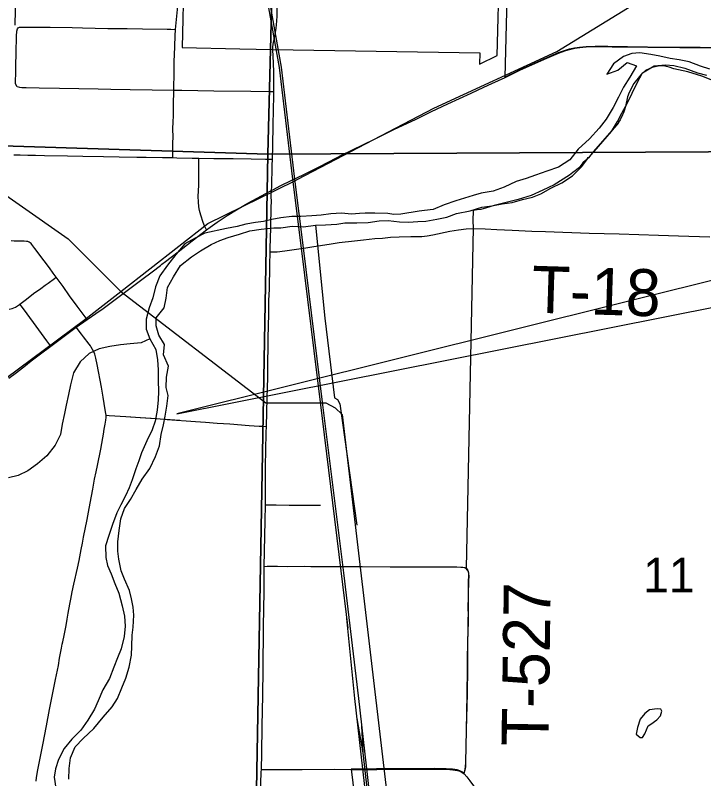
# Model space of a CAD drawing. Extents: x 0 to 34, y 0 to 22.
# Drawn here: x 4.781 to 5.615, y 16.776 to 17.701 of the extents above; entities that cross this region are included whole.
import ezdxf

# ---------------------------------------------------------------- set-up
doc = ezdxf.new("R2010")
doc.units = 0
for name, color, linetype in [('GM_X_City_Street', 7, 'Continuous'), ('GM_X_Corporation', 7, 'Continuous'), ('GM_X_County_Road', 7, 'Continuous'), ('GM_X_Major_River', 7, 'Continuous'), ('GM_X_Minor_Lake', 7, 'Continuous'), ('GM_X_Minor_River', 7, 'Continuous'), ('GM_X_Rail_Line', 7, 'Continuous'), ('GM_X_Section', 7, 'Continuous'), ('GM_X_Section_Text', 7, 'Continuous'), ('GM_X_State_Route', 7, 'Continuous'), ('GM_X_Township_Road', 7, 'Continuous'), ('GM_X_Township_Road_Text', 7, 'Continuous'), ('SH_Data', 7, 'Continuous'), ('SH_Text', 7, 'Continuous')]:
    doc.layers.add(name, color=color, linetype=linetype)

msp = doc.modelspace()

# ---------------------------------------------------------------- linework, layer by layer
at = {"layer": 'GM_X_City_Street'}
for points in [[(4.9721, 17.52836), (4.9721, 17.53093), (4.97209, 17.5371), (4.97221, 17.54142), (4.97234, 17.54648), (4.97246, 17.55277), (4.97234, 17.56374), (4.97258, 17.57128), (4.97282, 17.57917), (4.97294, 17.58398), (4.97304, 17.59172), (4.97342, 17.61006), (4.97346, 17.61194), (4.97374, 17.6306), (4.97399, 17.64462), (4.97445, 17.66196), (4.97448, 17.66329), (4.97499, 17.67571), (4.97561, 17.68363), (4.97873, 17.71603)], [(4.78357, 17.61461), (4.78234, 17.61609), (4.78176, 17.61807), (4.78205, 17.63367), (4.78258, 17.66125), (4.78293, 17.66951), (4.78293, 17.67556), (4.78318, 17.68136), (4.78391, 17.6842), (4.7849, 17.68555)], [(4.7849, 17.68555), (4.78663, 17.68642), (4.78935, 17.68658), (4.80034, 17.68636), (4.8237, 17.68632), (4.85015, 17.68587), (4.86261, 17.68573), (4.89362, 17.68496), (4.90485, 17.68484), (4.91698, 17.6847), (4.93565, 17.68446), (4.96522, 17.68402), (4.9699, 17.68385), (4.97561, 17.68363)], [(4.78357, 17.61461), (4.78629, 17.6135), (4.78913, 17.61322), (4.79466, 17.61317), (4.8102, 17.61291), (4.83508, 17.61255), (4.88172, 17.61149), (4.89727, 17.6113), (4.92059, 17.61082), (4.94702, 17.61058), (4.97342, 17.61006), (4.98295, 17.60988), (5.02182, 17.6094), (5.06685, 17.60892), (5.08931, 17.60856), (5.09466, 17.60847)], [(4.7795, 17.53182), (4.78716, 17.53158), (4.79658, 17.53136), (4.80591, 17.53117), (4.81679, 17.53098), (4.84475, 17.5304), (4.86338, 17.53005), (4.88826, 17.52953), (4.90733, 17.5294), (4.92879, 17.52904), (4.94002, 17.52879), (4.95979, 17.5286), (4.9721, 17.52836), (4.97689, 17.52826), (4.99555, 17.52772), (5.00364, 17.52764), (5.02201, 17.52743), (5.04535, 17.52715), (5.06713, 17.52671), (5.08426, 17.52647), (5.09275, 17.52636)], [(5.01283, 17.44071), (5.01061, 17.44577), (5.00884, 17.44966), (5.00605, 17.45845), (5.00456, 17.46437), (5.00377, 17.46887), (5.00316, 17.47493), (5.00301, 17.48104), (5.00359, 17.49493), (5.00363, 17.51965), (5.00364, 17.52764)], [(4.86852, 17.3321), (4.86379, 17.33857), (4.8565, 17.34855), (4.84721, 17.36086), (4.83919, 17.37218), (4.83107, 17.38343), (4.82743, 17.38847), (4.82283, 17.39471), (4.81623, 17.40325), (4.80513, 17.4181), (4.80152, 17.42315), (4.80046, 17.42428), (4.79928, 17.42524), (4.79799, 17.42604), (4.79657, 17.42653), (4.79509, 17.42684), (4.79201, 17.42706), (4.79045, 17.42706), (4.78742, 17.42713), (4.78297, 17.42723), (4.78016, 17.42722), (4.77621, 17.42734)], [(4.77413, 17.34484), (4.77771, 17.34558), (4.78154, 17.34719), (4.78633, 17.35037), (4.78704, 17.35091), (4.79501, 17.35697), (4.80357, 17.36364), (4.81226, 17.36974), (4.81744, 17.37369), (4.82118, 17.37638), (4.82904, 17.38184), (4.83107, 17.38343)], [(4.82438, 17.29984), (4.81969, 17.30631), (4.80686, 17.32399), (4.79571, 17.33901), (4.79019, 17.34658), (4.78704, 17.35091)], [(4.89136, 17.21619), (4.89525, 17.21591), (4.91546, 17.21452), (4.93258, 17.21348), (4.95279, 17.21208), (4.96522, 17.21117), (4.99946, 17.20881), (5.01188, 17.20792), (5.02603, 17.20674), (5.04132, 17.20564), (5.06461, 17.2037), (5.07072, 17.20328), (5.07683, 17.20301), (5.07992, 17.20288), (5.08553, 17.20265)], [(5.08427, 17.10755), (5.08842, 17.10752), (5.09725, 17.10747), (5.11292, 17.1073), (5.1333, 17.10734), (5.15105, 17.10712)], [(5.08298, 17.03316), (5.08647, 17.03317), (5.09913, 17.03319), (5.11149, 17.03305), (5.13164, 17.03321), (5.13939, 17.03315), (5.15333, 17.03312), (5.16416, 17.03309), (5.17655, 17.03298), (5.20135, 17.0328), (5.23547, 17.03267), (5.2541, 17.03275), (5.27272, 17.03263), (5.30066, 17.03262), (5.31621, 17.03248), (5.3209, 17.03223), (5.32332, 17.03209), (5.32579, 17.0316), (5.32764, 17.03036)]]:
    msp.add_lwpolyline(points, dxfattribs=at)
at = {"layer": 'GM_X_Corporation'}
for points in [[(5.37874, 17.8017), (5.37438, 17.6259), (5.3924, 17.63466), (5.42211, 17.64814), (5.43923, 17.65554), (5.44655, 17.65831), (5.45258, 17.66007), (5.4587, 17.6614), (5.4649, 17.66231), (5.4727, 17.66295), (5.4836, 17.66333), (5.49915, 17.66336), (5.54727, 17.66274), (5.58608, 17.66234), (5.61092, 17.66226), (5.66991, 17.66187)], [(4.78131, 17.6888), (4.78335, 17.78148)], [(4.98537, 17.74948), (4.98368, 17.66159), (5.05314, 17.65999), (5.09309, 17.65929), (5.34411, 17.6551), (5.34369, 17.64148), (5.36489, 17.65212), (5.36787, 17.75895)], [(5.64234, 17.61548), (5.6127, 17.6272), (5.59609, 17.6321), (5.57916, 17.63589), (5.57323, 17.63811), (5.56823, 17.63911), (5.56276, 17.63939), (5.5598, 17.63918), (5.55274, 17.63762), (5.54471, 17.63373), (5.53886, 17.62878), (5.53048, 17.61828), (5.5248, 17.60727), (5.52295, 17.60194), (5.52035, 17.59023), (5.51916, 17.58612), (5.51791, 17.58272), (5.51684, 17.58009), (5.51389, 17.57417), (5.51207, 17.57113), (5.51207, 17.57059), (5.51152, 17.57026), (5.51003, 17.56805), (5.48141, 17.53541), (5.47551, 17.52814), (5.47453, 17.52812), (5.47373, 17.52638), (5.47302, 17.52548), (5.47186, 17.52475), (5.46886, 17.52201), (5.46511, 17.51707), (5.46345, 17.51543), (5.45947, 17.51235), (5.45658, 17.51043), (5.45257, 17.50709), (5.43384, 17.49521), (5.42028, 17.4888), (5.40629, 17.48246), (5.39036, 17.47767), (5.36151, 17.47037), (5.35217, 17.46747), (5.34525, 17.46568), (5.34081, 17.4651), (5.33612, 17.46418), (5.33556, 17.45181), (5.33581, 17.44314), (5.32741, 17.03091), (5.3289, 17.02906), (5.32989, 17.02734), (5.33038, 17.02463), (5.3305, 17.0208), (5.33024, 17.01651), (5.3301, 17.0103), (5.32995, 17.00416), (5.33004, 16.99636), (5.32981, 16.98396), (5.32986, 16.97465), (5.32981, 16.96998), (5.32982, 16.96383), (5.32979, 16.96075), (5.32967, 16.9592), (5.3295, 16.95303), (5.32923, 16.94374), (5.32926, 16.9391), (5.32919, 16.93755), (5.32899, 16.92515), (5.32895, 16.90961), (5.32854, 16.87854), (5.32749, 16.83507), (5.32705, 16.81487), (5.32672, 16.79628), (5.32647, 16.79073), (5.3261, 16.78789), (5.32472, 16.78233), (5.32226, 16.78414), (5.31979, 16.78546), (5.31653, 16.78652), (5.31098, 16.7873), (5.30324, 16.78785), (5.28922, 16.78814), (5.24545, 16.78791), (5.21888, 16.78767), (5.20324, 16.78757), (5.18831, 16.78757), (5.21928, 16.53187)]]:
    msp.add_lwpolyline(points, dxfattribs=at)
at = {"layer": 'GM_X_County_Road'}
for points in [[(5.09332, 17.65874), (5.09333, 17.6621), (5.09357, 17.6658), (5.0953, 17.67333), (5.09751, 17.68493), (5.09789, 17.6895), (5.09826, 17.6937), (5.0985, 17.69996), (5.09821, 17.73265), (5.0986, 17.75752), (5.09899, 17.79486), (5.10019, 17.85551), (5.10099, 17.89282), (5.10153, 17.91927), (5.10265, 17.97059), (5.10322, 18.01415), (5.10427, 18.05924), (5.10487, 18.09347), (5.106, 18.13856), (5.10817, 18.22373)], [(5.09466, 17.60847), (5.09471, 17.62083), (5.0944, 17.63162), (5.0941, 17.64298), (5.09332, 17.65874)], [(5.09275, 17.52636), (5.09328, 17.54202), (5.09382, 17.56829), (5.09415, 17.58531), (5.09464, 17.60385), (5.09466, 17.60847)], [(5.09183, 17.48872), (5.09193, 17.49312), (5.09249, 17.51884), (5.09275, 17.52636)], [(5.08995, 17.41439), (5.09001, 17.41834), (5.0907, 17.44322), (5.09147, 17.46961), (5.09149, 17.474), (5.09145, 17.48239), (5.09183, 17.48872)], [(5.08553, 17.20265), (5.0863, 17.23731), (5.08706, 17.26208), (5.08711, 17.27903), (5.08745, 17.3005), (5.08773, 17.30973), (5.08826, 17.33919), (5.08852, 17.35471), (5.08881, 17.36246), (5.08908, 17.36866), (5.08969, 17.39814), (5.08995, 17.41439)], [(4.87239, 17.3002), (4.87075, 17.30252), (4.86398, 17.31106), (4.86149, 17.31435), (4.85507, 17.32299)], [(4.89136, 17.21619), (4.89118, 17.21817), (4.8903, 17.22279), (4.88781, 17.23813), (4.88562, 17.25038), (4.88048, 17.27788), (4.87885, 17.28553), (4.87757, 17.29009), (4.87647, 17.29307), (4.87509, 17.29592), (4.87348, 17.29865), (4.87239, 17.3002)], [(4.80664, 16.77285), (4.80721, 16.77741), (4.80885, 16.78652), (4.8112, 16.79871), (4.81493, 16.81699), (4.81928, 16.83987), (4.82301, 16.85969), (4.8301, 16.89619), (4.83353, 16.91291), (4.83508, 16.92208), (4.83629, 16.92813), (4.83744, 16.93419), (4.83827, 16.93875), (4.83888, 16.94177), (4.8404, 16.94933), (4.8428, 16.96145), (4.84412, 16.96903), (4.84544, 16.97651), (4.84743, 16.98713), (4.8486, 16.9932), (4.85047, 17.00231), (4.85234, 17.01142), (4.85672, 17.03108), (4.85862, 17.04015), (4.86119, 17.05363), (4.86259, 17.06111), (4.86413, 17.06852), (4.86834, 17.08979), (4.86999, 17.09897), (4.87189, 17.10968), (4.87512, 17.12645), (4.87739, 17.13863), (4.87931, 17.14771), (4.88091, 17.15529), (4.88485, 17.17508), (4.88736, 17.1888), (4.88808, 17.19335), (4.88911, 17.19952), (4.89008, 17.2056), (4.89095, 17.2102), (4.89137, 17.2134), (4.89136, 17.21619)], [(5.08427, 17.10755), (5.0843, 17.11162), (5.08439, 17.1256), (5.08422, 17.13489), (5.0843, 17.14418), (5.08455, 17.15504), (5.08475, 17.17364), (5.08537, 17.19538), (5.08553, 17.20265)], [(5.08298, 17.03316), (5.08409, 17.08831), (5.08427, 17.10755)], [(5.07944, 16.78703), (5.07983, 16.80697), (5.08051, 16.83961), (5.08116, 16.87692), (5.0817, 16.90799), (5.08214, 16.95929), (5.0824, 16.98262), (5.08274, 17.00126), (5.08284, 17.02614), (5.08298, 17.03316)], [(5.07546, 16.53152), (5.0754, 16.53717), (5.07522, 16.54738), (5.07582, 16.60491), (5.07641, 16.64222), (5.07725, 16.69974), (5.07827, 16.74326), (5.07856, 16.75725), (5.07937, 16.78366), (5.07944, 16.78703)]]:
    msp.add_lwpolyline(points, dxfattribs=at)
at = {"layer": 'GM_X_Major_River'}
for points in [[(5.62271, 17.6356), (5.61144, 17.63929), (5.59756, 17.64456), (5.5855, 17.64675), (5.57456, 17.64853), (5.56213, 17.65111), (5.5512, 17.65327), (5.53761, 17.65512), (5.52813, 17.65459), (5.5182, 17.65104), (5.50585, 17.64185), (5.49797, 17.62952), (5.51134, 17.63413), (5.52256, 17.64372), (5.53382, 17.63965), (5.52552, 17.62581), (5.51803, 17.61385), (5.51205, 17.60147), (5.50568, 17.5891), (5.49686, 17.57489), (5.4884, 17.56409), (5.47671, 17.55109), (5.46315, 17.53852), (5.45298, 17.52548), (5.43913, 17.51671), (5.42499, 17.51174), (5.41124, 17.50714), (5.40016, 17.50323), (5.38795, 17.49936), (5.37339, 17.4925)], [(5.19509, 17.44938), (5.20874, 17.44981), (5.22204, 17.45177), (5.23303, 17.45226), (5.24687, 17.45067), (5.25753, 17.45023), (5.26898, 17.45101), (5.27846, 17.45154), (5.29177, 17.45387), (5.30395, 17.45623), (5.31579, 17.4605), (5.33216, 17.4639), (5.34628, 17.46811), (5.35845, 17.47009), (5.371, 17.47244), (5.38316, 17.47405), (5.39574, 17.47753), (5.40793, 17.48027), (5.41788, 17.48459), (5.43017, 17.4915), (5.4432, 17.49764), (5.45629, 17.50643), (5.46757, 17.51758), (5.47499, 17.52723), (5.4855, 17.53912), (5.49288, 17.54779), (5.50353, 17.55979), (5.51093, 17.5719), (5.51611, 17.58202), (5.52286, 17.59476), (5.53404, 17.61802), (5.54118, 17.63112), (5.55502, 17.63952), (5.56906, 17.6407), (5.5789, 17.64008), (5.59245, 17.63671), (5.60745, 17.63104), (5.61836, 17.62811)], [(5.37339, 17.4925), (5.36002, 17.48789), (5.34556, 17.4852), (5.33603, 17.4824), (5.32535, 17.47924), (5.31504, 17.47608), (5.30091, 17.47111), (5.28751, 17.46536), (5.27707, 17.46423), (5.27041, 17.46333), (5.2482, 17.45977), (5.23977, 17.45933), (5.23248, 17.46062), (5.21667, 17.46109), (5.20512, 17.46109), (5.1984, 17.46069), (5.18853, 17.45979), (5.17644, 17.46084), (5.16355, 17.46039), (5.15177, 17.45878), (5.14039, 17.45792), (5.12741, 17.45685), (5.1163, 17.45706), (5.10298, 17.4555), (5.09219, 17.4534), (5.0819, 17.45099), (5.0724, 17.4497), (5.06061, 17.44771), (5.04994, 17.44493), (5.03701, 17.44259), (5.01111, 17.43676), (4.99922, 17.4306), (4.98656, 17.42408), (4.97563, 17.41106), (4.96584, 17.39801), (4.95643, 17.38496), (4.95118, 17.3718), (4.94782, 17.3586), (4.94335, 17.34618), (4.93999, 17.3326), (4.94006, 17.32046), (4.94431, 17.30859)], [(4.84627, 16.77547), (4.84659, 16.78836), (4.84842, 16.80122), (4.85405, 16.81437), (4.86377, 16.82438), (4.87656, 16.83659), (4.88789, 16.85036), (4.89881, 16.863), (4.90511, 16.87309), (4.91035, 16.88587), (4.91519, 16.89752), (4.91931, 16.91108), (4.92199, 16.92536), (4.92259, 16.93643), (4.92292, 16.9497), (4.9243, 16.95954), (4.92504, 16.97394), (4.92414, 16.98383), (4.92212, 16.99375), (4.91972, 17.00405), (4.91362, 17.01748), (4.90971, 17.02783), (4.90665, 17.04194), (4.90575, 17.05145), (4.90565, 17.06284), (4.90713, 17.07647), (4.90938, 17.09084), (4.91385, 17.10325), (4.92093, 17.11408), (4.92768, 17.12644), (4.93518, 17.13879), (4.94421, 17.15185), (4.95138, 17.1661), (4.95588, 17.17927), (4.95811, 17.19288), (4.96105, 17.20458), (4.96283, 17.21516), (4.96502, 17.22725), (4.96647, 17.24012), (4.96406, 17.24967), (4.96437, 17.26218), (4.96698, 17.27578), (4.96088, 17.28921), (4.96195, 17.30209), (4.95541, 17.31325), (4.9519, 17.32434), (4.95214, 17.33421), (4.96154, 17.3465), (4.9641, 17.35821), (4.96555, 17.37107), (4.97306, 17.3838), (4.98136, 17.39764), (4.99488, 17.40832), (5.00566, 17.41527), (5.01872, 17.42292), (5.02907, 17.42798), (5.03938, 17.43152), (5.05274, 17.43576), (5.06534, 17.43962), (5.07902, 17.44157), (5.09455, 17.44328), (5.10298, 17.44329), (5.1166, 17.44521), (5.13059, 17.4445), (5.14517, 17.44641), (5.15716, 17.44686), (5.17081, 17.44769), (5.18032, 17.44936), (5.19509, 17.44938)], [(4.94431, 17.30859), (4.93397, 17.30391), (4.92069, 17.30271), (4.90892, 17.30148), (4.89599, 17.29951), (4.88305, 17.29679), (4.87079, 17.29102), (4.85994, 17.28103), (4.85203, 17.26756), (4.84827, 17.25323), (4.8457, 17.24115), (4.8431, 17.22831), (4.84097, 17.21849), (4.83799, 17.20528), (4.83616, 17.1928), (4.82979, 17.18005), (4.81962, 17.16702), (4.8084, 17.15742), (4.79645, 17.14898), (4.78495, 17.14319), (4.77314, 17.14043)], [(4.94431, 17.30859), (4.95157, 17.29589), (4.95353, 17.28332), (4.95437, 17.27115), (4.95443, 17.25825), (4.95485, 17.24495), (4.9546, 17.23471), (4.95315, 17.22222), (4.95093, 17.20899), (4.94726, 17.19846), (4.94088, 17.18533), (4.93433, 17.17053), (4.93081, 17.16091), (4.92753, 17.15112), (4.92304, 17.13794), (4.91939, 17.12816), (4.91498, 17.1184), (4.90941, 17.10753), (4.90425, 17.09779), (4.89898, 17.08387), (4.89449, 17.0707), (4.89076, 17.05789), (4.89117, 17.04384), (4.8932, 17.0343), (4.89749, 17.02395), (4.90213, 17.01245), (4.90676, 17.00057), (4.91093, 16.98529), (4.91364, 16.9727), (4.91448, 16.96054), (4.91341, 16.94804), (4.90955, 16.93335), (4.9052, 16.92243), (4.90068, 16.91114), (4.89549, 16.89723), (4.88757, 16.88339), (4.88157, 16.87025), (4.87715, 16.86011), (4.86924, 16.84664), (4.86061, 16.8347), (4.84974, 16.82396), (4.84075, 16.81241), (4.83361, 16.7993), (4.82992, 16.78801), (4.82853, 16.77779), (4.83047, 16.76446)]]:
    msp.add_lwpolyline(points, dxfattribs=at)
at = {"layer": 'GM_X_Minor_Lake'}
msp.add_line((5.54807, 16.84005), (5.55115, 16.84187), dxfattribs=at)
msp.add_lwpolyline([(5.55115, 16.84187), (5.55847, 16.84701), (5.56276, 16.85184), (5.56441, 16.85749), (5.56334, 16.86017), (5.55881, 16.86066), (5.54969, 16.85936), (5.5439, 16.85495), (5.53804, 16.84788), (5.53476, 16.83771), (5.53343, 16.82978), (5.53826, 16.82586), (5.5409, 16.8258), (5.54366, 16.83029), (5.54606, 16.83516), (5.54807, 16.84005)], dxfattribs=at)
at = {"layer": 'GM_X_Minor_River'}
msp.add_lwpolyline([(5.14517, 17.44641), (5.15625, 17.33381), (5.16786, 17.23714), (5.1716, 17.23515), (5.17451, 17.23014), (5.1951, 17.08315)], dxfattribs=at)
at = {"layer": 'GM_X_Rail_Line'}
for p, q in [((5.1199, 17.50035), (5.1236, 17.50218)), ((5.1536, 17.23105), (5.15751, 17.23105)), ((5.20264, 16.80706), (5.19551, 16.84896)), ((5.20264, 16.80706), (5.20112, 16.83979))]:
    msp.add_line(p, q, dxfattribs=at)
for points in [[(3.67316, 20.89996), (3.64713, 20.08996), (3.64713, 19.90807), (3.75204, 19.36586), (3.93257, 18.42273), (3.94904, 18.35551), (3.97539, 18.30014), (4.01163, 18.23292), (4.0712, 18.1586), (4.3307, 17.8397), (4.42818, 17.73428), (4.66304, 17.55761), (4.84551, 17.42995), (4.90926, 17.36618)], [(5.18454, 16.95829), (5.17593, 17.02755), (5.15118, 17.23187), (5.12784, 17.41859), (5.11734, 17.50206), (5.10136, 17.63753), (5.05806, 17.87976), (4.95141, 18.50436), (4.7757, 19.52024), (4.64618, 20.27618), (4.53847, 20.89996)], [(5.53295, 14.09996), (5.44137, 14.84523), (5.23677, 16.52912), (5.19731, 16.87301), (5.17943, 17.02529), (5.15365, 17.23215), (5.13031, 17.4189), (5.1198, 17.50236), (5.10382, 17.6379), (5.0605, 17.88018), (4.95386, 18.50478), (4.77815, 19.52067), (4.64863, 20.2766), (4.54099, 20.89996)], [(5.1236, 17.50218), (5.28849, 17.58821), (5.43721, 17.6568), (5.85805, 17.91529), (6.16286, 18.16113), (6.30419, 18.16429), (6.46873, 18.22655), (7.12953, 18.53496)], [(4.90926, 17.36618), (5.01473, 17.44847), (5.1199, 17.50035)], [(4.56196, 17.1188), (4.70452, 17.21275), (4.86559, 17.3321), (4.90926, 17.36618)], [(4.90926, 17.36618), (5.0848, 17.23114), (5.1536, 17.23105)], [(5.15751, 17.23105), (5.16895, 17.22536), (5.1772, 17.21711), (5.45561, 14.85531)], [(5.39721, 15.18806), (5.38092, 15.30154), (5.23183, 16.52852), (5.19278, 16.87301), (5.18312, 16.96977)], [(5.37213, 15.39351), (5.37201, 15.39545), (5.2343, 16.52882), (5.20264, 16.80706)]]:
    msp.add_lwpolyline(points, dxfattribs=at)
at = {"layer": 'GM_X_Section'}
for points in [[(4.13385, 18.51907), (5.11234, 18.51615), (5.08739, 17.53257), (4.65019, 17.54619), (4.08516, 17.54862), (4.10845, 18.51895)], [(5.13129, 18.51595), (6.09233, 18.50979), (6.07847, 17.53783), (5.08739, 17.53257), (5.11234, 18.51615)], [(5.08739, 17.53257), (5.0695, 16.53641), (4.06558, 16.53354), (4.08516, 17.54862), (4.65019, 17.54619)], [(6.07847, 17.53783), (6.06277, 16.53445), (5.0695, 16.53641), (5.08739, 17.53257)]]:
    msp.add_lwpolyline(points, close=True, dxfattribs=at)
at = {"layer": 'GM_X_State_Route'}
for points in [[(5.50439, 17.66274), (5.5475, 17.66218), (5.5863, 17.66178), (5.61114, 17.66171), (5.67013, 17.66132), (5.69653, 17.66123), (5.71827, 17.66091), (5.73535, 17.6606), (5.76328, 17.65976), (5.79122, 17.65939), (5.80516, 17.65946), (5.81439, 17.65996), (5.82047, 17.66083), (5.82496, 17.66178), (5.83086, 17.66347), (5.83661, 17.6656), (5.8408, 17.66749), (5.84486, 17.66964), (5.84877, 17.67206), (5.8525, 17.67475), (5.8566, 17.67806), (5.85956, 17.6809)], [(5.37461, 17.62535), (5.39263, 17.6341), (5.42234, 17.64759), (5.43946, 17.65499), (5.44677, 17.65775), (5.4528, 17.65952), (5.45893, 17.66085), (5.46513, 17.66176), (5.47292, 17.66239), (5.48383, 17.66278), (5.49937, 17.6628), (5.50439, 17.66274)], [(5.34873, 17.61359), (5.35869, 17.61823), (5.37461, 17.62535)], [(5.1704, 17.52798), (5.17653, 17.53113), (5.21552, 17.55041), (5.24062, 17.56273), (5.26592, 17.57465), (5.28551, 17.58403), (5.30508, 17.59355), (5.33334, 17.60641), (5.34873, 17.61359)], [(5.09007, 17.48778), (5.09183, 17.48872), (5.09323, 17.48946), (5.10293, 17.49439), (5.11547, 17.50053), (5.13081, 17.50801), (5.15029, 17.51765), (5.1704, 17.52798)], [(4.95904, 17.39916), (4.96337, 17.40257), (4.97855, 17.41417), (4.99569, 17.42763), (5.01283, 17.44071), (5.01739, 17.44417), (5.02578, 17.45022), (5.03799, 17.45812), (5.05119, 17.46615), (5.06316, 17.4733), (5.07949, 17.48216), (5.09007, 17.48778)], [(4.77375, 17.26122), (4.7828, 17.26811), (4.7936, 17.27632), (4.80065, 17.28208), (4.81185, 17.29067), (4.82438, 17.29984), (4.83584, 17.30822), (4.85507, 17.32299), (4.86852, 17.3321), (4.86963, 17.33286), (4.8791, 17.33935), (4.8878, 17.3457), (4.93474, 17.38071), (4.9471, 17.38989), (4.9573, 17.39779), (4.95904, 17.39916)]]:
    msp.add_lwpolyline(points, dxfattribs=at)
at = {"layer": 'GM_X_Township_Road'}
for points in [[(5.08995, 17.41439), (5.09225, 17.41432), (5.0985, 17.41416), (5.10795, 17.41549), (5.12481, 17.41765), (5.13093, 17.41854), (5.14313, 17.42059), (5.16147, 17.42367), (5.17377, 17.42537), (5.19225, 17.42765), (5.20302, 17.42893), (5.2169, 17.43018), (5.22627, 17.43093), (5.2359, 17.43204), (5.24638, 17.43229), (5.26027, 17.43272), (5.26644, 17.43278), (5.27377, 17.43292), (5.28019, 17.43366), (5.28698, 17.43465), (5.30759, 17.4392), (5.31834, 17.44097), (5.32761, 17.44211), (5.33604, 17.44259)], [(5.33604, 17.44259), (5.35043, 17.44224), (5.36468, 17.44145), (5.3833, 17.44031), (5.40692, 17.43916), (5.42371, 17.43865), (5.47652, 17.43699), (5.51258, 17.43586), (5.56043, 17.43451), (5.58466, 17.43365), (5.62257, 17.43235)], [(5.32495, 16.78178), (5.32633, 16.78734), (5.3267, 16.79018), (5.32694, 16.79573), (5.32728, 16.81432), (5.32772, 16.83451), (5.32877, 16.87798), (5.32918, 16.90906), (5.32922, 16.9246), (5.32942, 16.93699), (5.32948, 16.93855), (5.32946, 16.94319), (5.32973, 16.95247), (5.3299, 16.95865), (5.33001, 16.9602), (5.33005, 16.96327), (5.33003, 16.96942), (5.33009, 16.9741), (5.33004, 16.98341), (5.33027, 16.99581), (5.33018, 17.0036), (5.33032, 17.00975), (5.33047, 17.01595), (5.33073, 17.02024), (5.3306, 17.02407), (5.33011, 17.02679), (5.32912, 17.02851), (5.32764, 17.03036)], [(5.07944, 16.78703), (5.0836, 16.78707), (5.09117, 16.78713), (5.09746, 16.7869), (5.12876, 16.78704), (5.16783, 16.78722), (5.18853, 16.78701)], [(5.18853, 16.78701), (5.20347, 16.78701), (5.2191, 16.78712), (5.24567, 16.78736), (5.28944, 16.78759), (5.30346, 16.7873), (5.3112, 16.78675), (5.31676, 16.78596), (5.32001, 16.7849), (5.32248, 16.78358), (5.32495, 16.78178)], [(5.32495, 16.78178), (5.32824, 16.77832), (5.33201, 16.77315), (5.33757, 16.7656), (5.34023, 16.76178), (5.35207, 16.74541), (5.36107, 16.73275), (5.3692, 16.72139), (5.38395, 16.70139), (5.39683, 16.68384), (5.40404, 16.67373), (5.41668, 16.65605), (5.42511, 16.64492), (5.43761, 16.62907), (5.4442, 16.62041), (5.45256, 16.60922), (5.46579, 16.59198), (5.47716, 16.57722), (5.49333, 16.55634), (5.50945, 16.53541), (5.51508, 16.52794)]]:
    msp.add_lwpolyline(points, dxfattribs=at)
at = {"layer": 'SH_Data'}
msp.add_line((4.91546, 17.21452), (4.98051, 17.21012), dxfattribs=at)
at = {"layer": 'SH_Text'}
msp.add_lwpolyline([(9.31108, 18.29898), (4.97713, 17.21812), (9.31108, 18.08015)], close=True, dxfattribs=at)

# ---------------------------------------------------------------- texts
at = {"layer": 'GM_X_Section_Text'}
msp.add_text('11', height=0.041856, rotation=0.00001, dxfattribs=at).set_placement((5.54173, 17.00172))
at = {"layer": 'GM_X_Township_Road_Text'}
for s, rotation, p in [('T-18', 358.23292, (5.40608, 17.34059)), ('T-527', 89.1569, (5.42701, 16.81486))]:
    msp.add_text(s, height=0.056818, rotation=rotation, dxfattribs=at).set_placement(p)

doc.saveas('drawing.dxf')
